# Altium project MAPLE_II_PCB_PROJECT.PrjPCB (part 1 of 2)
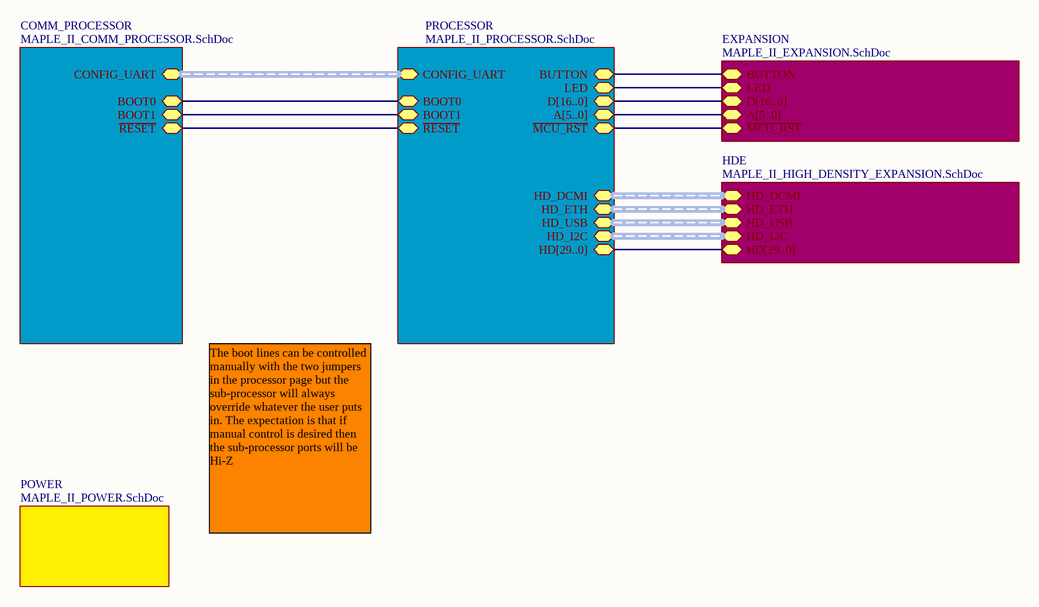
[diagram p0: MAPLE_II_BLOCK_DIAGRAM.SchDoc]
Revision: A; Number: Maple II; Engineer: Dave McCoy; Drawn: Dave McCoy; Company: Leaflabs LLC
6 sheets, 140 parts. Net scope: hierarchical (ports join the sheet entries above them; power ports are global).
Board file: MAPLE_II.PcbDoc
Sheets:
  MAPLE_II_BLOCK_DIAGRAM.SchDoc
    PROCESSOR = MAPLE_II_PROCESSOR.SchDoc
    COMM_PROCESSOR = MAPLE_II_COMM_PROCESSOR.SchDoc
    POWER = MAPLE_II_POWER.SchDoc
    EXPANSION = MAPLE_II_EXPANSION.SchDoc
    HDE = MAPLE_II_HIGH_DENSITY_EXPANSION.SchDoc

## Sheet MAPLE_II_BLOCK_DIAGRAM.SchDoc: Block Diagram
size B; CompanyName: LeafLabs; DrawnBy: David McCoy; Engineer: David McCoy; Organization: LeafLabs; DocumentNumber: 1; Revision: A; SheetNumber: 1; SheetTotal: 6; ProjectPrettyName: Maple II

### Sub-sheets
COMM_PROCESSOR = MAPLE_II_COMM_PROCESSOR.SchDoc: ~{RESET}, BOOT0, BOOT1, CONFIG_UART (harness UART_Harness)
EXPANSION = MAPLE_II_EXPANSION.SchDoc: BUTTON, LED, A[5..0], D[16..0], ~{MCU_RST}
HDE = MAPLE_II_HIGH_DENSITY_EXPANSION.SchDoc: HD_DCMI (harness DCMI_Harness), HD_ETH (harness ETH_RMII_Harness), HD_USB (harness USB_Harness), HD_I2C (harness I2C_Harness), HD[29..0]
POWER = MAPLE_II_POWER.SchDoc: no entries
PROCESSOR = MAPLE_II_PROCESSOR.SchDoc: ~{RESET}, BOOT0, BOOT1, CONFIG_UART (harness UART_Harness), BUTTON, LED, HD_DCMI (harness DCMI_Harness), HD_ETH (harness ETH_RMII_Harness), HD_USB (harness USB_Harness), HD_I2C (harness I2C_Harness), A[5..0], D[16..0], HD[29..0], ~{MCU_RST}

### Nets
BOOT0: sheet PROCESSOR/BOOT0, sheet PROCESSOR/BUTTON, sheet COMM_PROCESSOR/BOOT0, sheet EXPANSION/BUTTON
BOOT1: sheet PROCESSOR/BOOT1, sheet COMM_PROCESSOR/BOOT1
D13: sheet PROCESSOR/LED, sheet EXPANSION/LED
~{MCU_RST}: sheet PROCESSOR/~{MCU_RST}, sheet EXPANSION/~{MCU_RST}
NetR22_2: sheet PROCESSOR/~{RESET}, sheet COMM_PROCESSOR/~{RESET}

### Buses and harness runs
bus sheet EXPANSION/A[5..0] = sheet PROCESSOR/A[5..0]
bus sheet EXPANSION/D[16..0] = sheet PROCESSOR/D[16..0]
bus sheet HDE/HD[29..0] = sheet PROCESSOR/HD[29..0]
harness sheet COMM_PROCESSOR/CONFIG_UART = sheet PROCESSOR/CONFIG_UART
harness sheet HDE/HD_DCMI = sheet PROCESSOR/HD_DCMI
harness sheet HDE/HD_ETH = sheet PROCESSOR/HD_ETH
harness sheet HDE/HD_I2C = sheet PROCESSOR/HD_I2C
harness sheet HDE/HD_USB = sheet PROCESSOR/HD_USB

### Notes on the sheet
- The boot lines can be controlled manually with the two jumpers in the processor page but the sub-processor will always override whatever the user puts in. The expectation is that if manual control is desired then the sub-processor ports will be Hi-Z

## Sheet MAPLE_II_PROCESSOR.SchDoc: Processor
size B; CompanyName: LeafLabs; DrawnBy: David McCoy; Engineer: David McCoy; Organization: LeafLabs; DocumentNumber: 3; Revision: A; SheetNumber: 3; SheetTotal: 6; ProjectPrettyName: Maple II
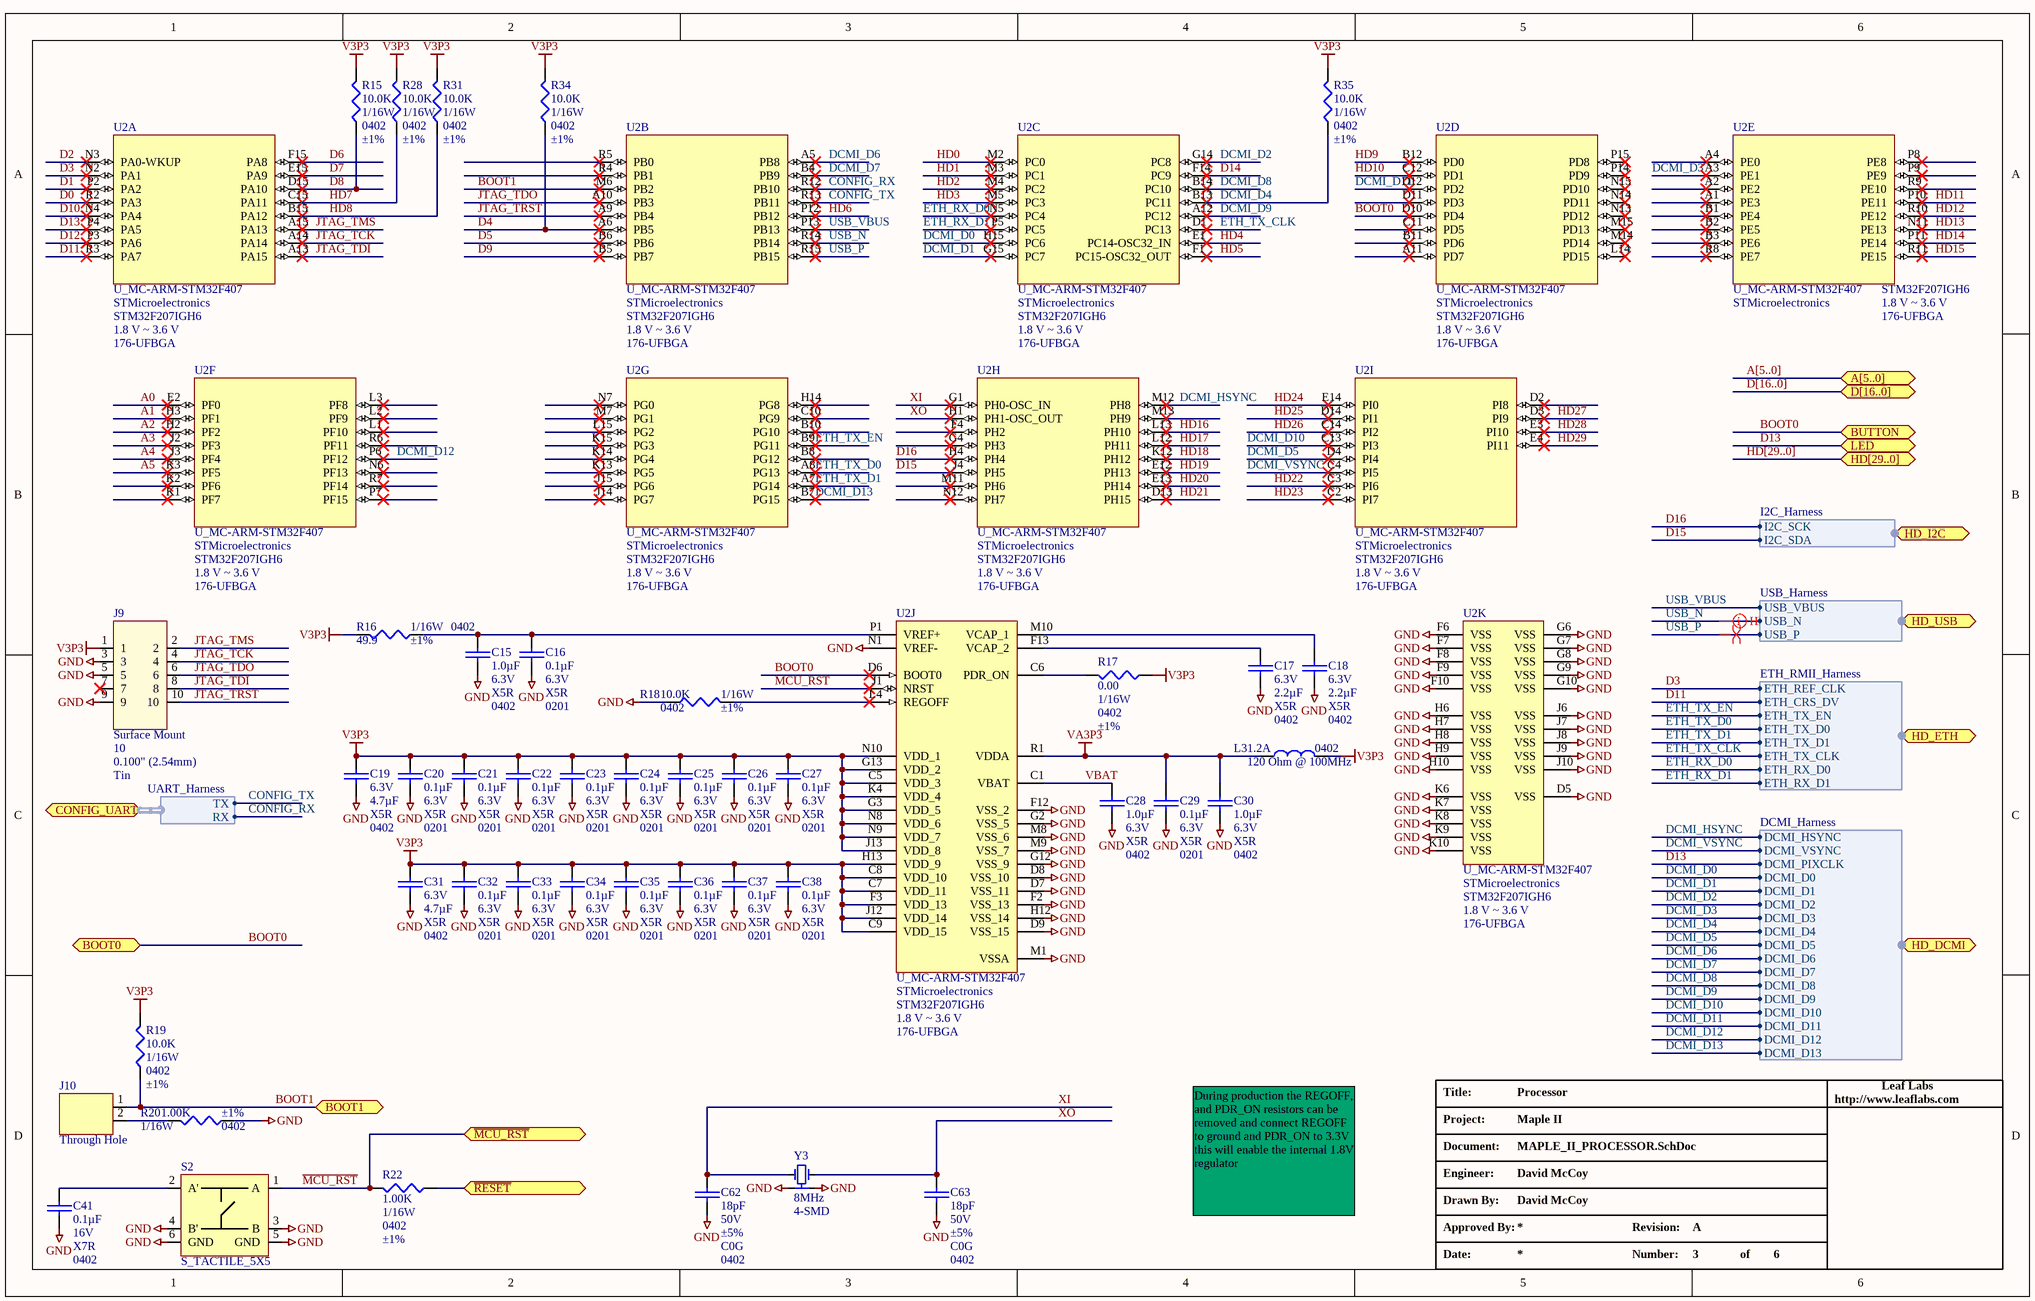
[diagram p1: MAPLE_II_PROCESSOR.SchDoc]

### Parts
(Parts that share a designator on the sheet are numbered #1, #2 ... from top to bottom, then left to right.)
C15  Capacitance: 1.0µF  Voltage - Rated: 6.3V  Temperature Coefficient: X5R  Package / Case: 0402  [CAPC0201]  (hidden comment: 1.0UF)
C16  Capacitance: 0.1µF  Voltage - Rated: 6.3V  Temperature Coefficient: X5R  Package / Case: 0201  [CAPC0201]  (hidden comment: 0.1UF)
C17  Voltage - Rated: 6.3V  Capacitance: 2.2µF  Temperature Coefficient: X5R  Package / Case: 0402  [C_ERA-0402]  (hidden comment: Capacitor 2.2uF 0402)
C18  Voltage - Rated: 6.3V  Capacitance: 2.2µF  Temperature Coefficient: X5R  Package / Case: 0402  [C_ERA-0402]  (hidden comment: Capacitor 2.2uF 0402)
C19  Voltage - Rated: 6.3V  Capacitance: 4.7µF  Temperature Coefficient: X5R  Package / Case: 0402  [C_ERA-0402]  (hidden comment: Capacitor  4.7uF 0402)
C20  Capacitance: 0.1µF  Voltage - Rated: 6.3V  Temperature Coefficient: X5R  Package / Case: 0201  [CAPC0201]  (hidden comment: 0.1UF)
C21  Capacitance: 0.1µF  Voltage - Rated: 6.3V  Temperature Coefficient: X5R  Package / Case: 0201  [CAPC0201]  (hidden comment: 0.1UF)
C22  Capacitance: 0.1µF  Voltage - Rated: 6.3V  Temperature Coefficient: X5R  Package / Case: 0201  [CAPC0201]  (hidden comment: 0.1UF)
C23  Capacitance: 0.1µF  Voltage - Rated: 6.3V  Temperature Coefficient: X5R  Package / Case: 0201  [CAPC0201]  (hidden comment: 0.1UF)
C24  Capacitance: 0.1µF  Voltage - Rated: 6.3V  Temperature Coefficient: X5R  Package / Case: 0201  [CAPC0201]  (hidden comment: 0.1UF)
C25  Capacitance: 0.1µF  Voltage - Rated: 6.3V  Temperature Coefficient: X5R  Package / Case: 0201  [CAPC0201]  (hidden comment: 0.1UF)
C26  Capacitance: 0.1µF  Voltage - Rated: 6.3V  Temperature Coefficient: X5R  Package / Case: 0201  [CAPC0201]  (hidden comment: 0.1UF)
C27  Capacitance: 0.1µF  Voltage - Rated: 6.3V  Temperature Coefficient: X5R  Package / Case: 0201  [CAPC0201]  (hidden comment: 0.1UF)
C28  Capacitance: 1.0µF  Voltage - Rated: 6.3V  Temperature Coefficient: X5R  Package / Case: 0402  [CAPC0201]  (hidden comment: 1.0UF)
C29  Capacitance: 0.1µF  Voltage - Rated: 6.3V  Temperature Coefficient: X5R  Package / Case: 0201  [CAPC0201]  (hidden comment: 0.1UF)
C30  Capacitance: 1.0µF  Voltage - Rated: 6.3V  Temperature Coefficient: X5R  Package / Case: 0402  [CAPC0201]  (hidden comment: 1.0UF)
C31  Voltage - Rated: 6.3V  Capacitance: 4.7µF  Temperature Coefficient: X5R  Package / Case: 0402  [C_ERA-0402]  (hidden comment: Capacitor  4.7uF 0402)
C32  Capacitance: 0.1µF  Voltage - Rated: 6.3V  Temperature Coefficient: X5R  Package / Case: 0201  [CAPC0201]  (hidden comment: 0.1UF)
C33  Capacitance: 0.1µF  Voltage - Rated: 6.3V  Temperature Coefficient: X5R  Package / Case: 0201  [CAPC0201]  (hidden comment: 0.1UF)
C34  Capacitance: 0.1µF  Voltage - Rated: 6.3V  Temperature Coefficient: X5R  Package / Case: 0201  [CAPC0201]  (hidden comment: 0.1UF)
C35  Capacitance: 0.1µF  Voltage - Rated: 6.3V  Temperature Coefficient: X5R  Package / Case: 0201  [CAPC0201]  (hidden comment: 0.1UF)
C36  Capacitance: 0.1µF  Voltage - Rated: 6.3V  Temperature Coefficient: X5R  Package / Case: 0201  [CAPC0201]  (hidden comment: 0.1UF)
C37  Capacitance: 0.1µF  Voltage - Rated: 6.3V  Temperature Coefficient: X5R  Package / Case: 0201  [CAPC0201]  (hidden comment: 0.1UF)
C38  Capacitance: 0.1µF  Voltage - Rated: 6.3V  Temperature Coefficient: X5R  Package / Case: 0201  [CAPC0201]  (hidden comment: 0.1UF)
C41  Capacitance: 0.1µF  Voltage - Rated: 16V  Temperature Coefficient: X7R  Package / Case: 0402  [C_ERA-0402]  (hidden comment: C_0402_0.1UF_16V)
C62  Capacitance: 18pF  Voltage - Rated: 50V  Tolerance: ±5%  Temperature Coefficient: C0G  Package / Case: 0402  [C_ERA-0402]  (hidden comment: Capacitor 18pF 0402)
C63  Capacitance: 18pF  Voltage - Rated: 50V  Tolerance: ±5%  Temperature Coefficient: C0G  Package / Case: 0402  [C_ERA-0402]  (hidden comment: Capacitor 18pF 0402)
J9  Mounting Type: Surface Mount  Number of Positions: 10  Pitch: 0.100" (2.54mm)  Contact Finish: Tin  [HDR_2X5_1.27MMSMD]  (hidden comment: J_HDR2X5_0.05_SMD)
J10  Mounting Type: Through Hole  [HDR_1X2]  (hidden comment: J_HDR1X2_JUMPER)
L3  Impedance @ Frequency: 120 Ohm @ 100MHz  Current Rating: 1.2A  Package / Case: 0402  [ERA-0402]  (hidden comment: L_FERRITE_120R_100MHZ)
R15  Resistance In Ohms: 10.0K  Power (Watts): 1/16W  Case: 0402  Tolerance: ±1%  [ERA-0402]  (hidden comment: R_0402_10.0K)
R16  Resistance (Ohms): 49.9  Power (Watts): 1/16W  Tolerance: ±1%  Package / Case: 0402  [ERA-0402]  (hidden comment: R_0402_49.9)
R17  Resistance In Ohms: 0.00  Power (Watts): 1/16W  Case: 0402  Tolerance: ±1%  [ERA-0402]  (hidden comment: R_0402_0.0)
R18  Resistance In Ohms: 10.0K  Power (Watts): 1/16W  Case: 0402  Tolerance: ±1%  [ERA-0402]  (hidden comment: R_0402_10.0K)
R19  Resistance In Ohms: 10.0K  Power (Watts): 1/16W  Case: 0402  Tolerance: ±1%  [ERA-0402]  (hidden comment: R_0402_10.0K)
R20  Resistance In Ohms: 1.00K  Power (Watts): 1/16W  Case: 0402  Tolerance: ±1%  [ERA-0402]  (hidden comment: R_0402_1.0K)
R22  Resistance In Ohms: 1.00K  Power (Watts): 1/16W  Case: 0402  Tolerance: ±1%  [ERA-0402]  (hidden comment: R_0402_1.0K)
R28  Resistance In Ohms: 10.0K  Power (Watts): 1/16W  Case: 0402  Tolerance: ±1%  [ERA-0402]  (hidden comment: R_0402_10.0K)
R31#1  Resistance In Ohms: 10.0K  Power (Watts): 1/16W  Case: 0402  Tolerance: ±1%  [ERA-0402]  (hidden comment: R_0402_10.0K)
R34#1  Resistance In Ohms: 10.0K  Power (Watts): 1/16W  Case: 0402  Tolerance: ±1%  [ERA-0402]  (hidden comment: R_0402_10.0K)
R35#1  Resistance In Ohms: 10.0K  Power (Watts): 1/16W  Case: 0402  Tolerance: ±1%  [ERA-0402]  (hidden comment: R_0402_10.0K)
S2  S_TACTILE_5X5  [TACTILE_BUTTON_5X5]
U2  U_MC-ARM-STM32F407  Manufacturer: STMicroelectronics  Manufacturer Part Number: STM32F207IGH6  Voltage - Supply (Vcc/Vdd): 1.8 V ~ 3.6 V  Package / Case: 176-UFBGA  [UFBGA176+25]  (parts A,B,C,D,E,F,G,H,I,J,K of 11)
Y3  Package / Case: 4-SMD  [SMD_OSC_8MHZ]  (hidden comment: 8MHz)

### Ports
A[5..0], BOOT0, BOOT1, BUTTON, CONFIG_UART (harness UART_Harness), D[16..0], HD[29..0], HD_DCMI (harness DCMI_Harness), HD_ETH (harness ETH_RMII_Harness), HD_I2C (harness I2C_Harness), HD_USB (harness USB_Harness), LED, ~{MCU_RST}, ~{RESET}

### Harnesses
UART_Harness: TX, RX
DCMI_Harness: DCMI_HSYNC, DCMI_VSYNC, DCMI_PIXCLK, DCMI_D0, DCMI_D1, DCMI_D2, DCMI_D3, DCMI_D4, DCMI_D5, DCMI_D6, DCMI_D7, DCMI_D8, DCMI_D9, DCMI_D10, DCMI_D11, DCMI_D12, DCMI_D13
ETH_RMII_Harness: ETH_REF_CLK, ETH_CRS_DV, ETH_TX_EN, ETH_TX_D0, ETH_TX_D1, ETH_TX_CLK, ETH_RX_D0, ETH_RX_D1
USB_Harness: USB_VBUS, USB_N, USB_P
I2C_Harness: I2C_SCK, I2C_SDA

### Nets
GND: C15.1 C16.1 C17.1 C18.1 C19.1 C20.1 C21.1 C22.1 C23.1 C24.1 C25.1 C26.1 C27.1 C28.1 C29.1 C30.1 C31.1 C32.1 C33.1 C34.1 C35.1 C36.1 C37.1 C38.1 C41.1 C62.1 C63.1 J9.3 J9.5 J9.9 R18.2 R20.2 S2.3(B) S2.4(B') S2.5(GND) S2.6(GND) U2.D5(VSS) U2.D7(VSS_11) U2.D8(VSS_10) U2.D9(VSS_15) U2.F2(VSS_13) U2.F6(VSS) U2.F7(VSS) U2.F8(VSS) U2.F9(VSS) U2.F10(VSS) U2.F12(VSS_2) U2.G2(VSS_5) U2.G6(VSS) U2.G7(VSS) U2.G8(VSS) U2.G9(VSS) U2.G10(VSS) U2.G12(VSS_9) U2.H6(VSS) U2.H7(VSS) U2.H8(VSS) U2.H9(VSS) U2.H10(VSS) U2.H12(VSS_14) U2.J6(VSS) U2.J7(VSS) U2.J8(VSS) U2.J9(VSS) U2.J10(VSS) U2.K6(VSS) U2.K7(VSS) U2.K8(VSS) U2.K9(VSS) U2.K10(VSS) U2.M1(VSSA) U2.M8(VSS_6) U2.M9(VSS_7) U2.N1(VREF-) Y3.2 Y3.4
V3P3: C19.2 C20.2 C21.2 C22.2 C23.2 C24.2 C25.2 C26.2 C27.2 C31.2 C32.2 C33.2 C34.2 C35.2 C36.2 C37.2 C38.2 J9.1 L3.2 R15.1 R16.1 R17.2 R19.2 R28.1 R31#1.1 R34#1.1 R35#1.1 U2.C5(VDD_3) U2.C7(VDD_11) U2.C8(VDD_10) U2.C9(VDD_15) U2.F3(VDD_13) U2.G3(VDD_5) U2.G13(VDD_2) U2.H13(VDD_9) U2.J12(VDD_14) U2.J13(VDD_8) U2.K4(VDD_4) U2.N8(VDD_6) U2.N9(VDD_7) U2.N10(VDD_1)
VA3P3: C29.2 C30.2 L3.1 U2.R1(VDDA)
A0: U2.E2(PF0)
A1: U2.H3(PF1)
A2: U2.H2(PF2)
A3: U2.J2(PF3)
A4: U2.J3(PF4)
A5: U2.K3(PF5)
BOOT0: U2.D6(BOOT0) U2.D10(PD4) ; port BOOT0, port BUTTON
BOOT1: J10.1 R19.1 U2.M6(PB2) ; port BOOT1
CONFIG_RX: U2.R12(PB10) ; port CONFIG_UART.RX  [project net COMM_UART1_RX]
CONFIG_TX: U2.R13(PB11) ; port CONFIG_UART.TX  [project net COMM_UART1_TX]
D0: U2.R2(PA3)
D1: U2.P2(PA2)
D2: U2.N3(PA0-WKUP)
D3: U2.N2(PA1) ; port HD_ETH.ETH_REF_CLK
D4: R34#1.2 U2.A6(PB5)
D5: U2.B6(PB6)
D6: U2.F15(PA8)
D7: U2.E15(PA9)
D8: R15.2 U2.D15(PA10)
D9: U2.B5(PB7)
D10: U2.N4(PA4)
D11: U2.R3(PA7) ; port HD_ETH.ETH_CRS_DV
D12: U2.P3(PA6)
D13: U2.P4(PA5) ; port LED, port HD_DCMI.DCMI_PIXCLK
D14: U2.F14(PC9)
D15: U2.J4(PH5) ; port HD_I2C.I2C_SDA
D16: U2.H4(PH4) ; port HD_I2C.I2C_SCK
DCMI_D0: U2.H15(PC6) ; port HD_DCMI.DCMI_D0
DCMI_D1: U2.G15(PC7) ; port HD_DCMI.DCMI_D1
DCMI_D2: U2.G14(PC8) ; port HD_DCMI.DCMI_D2
DCMI_D3: U2.A3(PE1) ; port HD_DCMI.DCMI_D3
DCMI_D4: R35#1.2 U2.B13(PC11) ; port HD_DCMI.DCMI_D4
DCMI_D5: U2.D4(PI4) ; port HD_DCMI.DCMI_D5
DCMI_D6: U2.A5(PB8) ; port HD_DCMI.DCMI_D6
DCMI_D7: U2.B4(PB9) ; port HD_DCMI.DCMI_D7
DCMI_D8: U2.B14(PC10) ; port HD_DCMI.DCMI_D8
DCMI_D9: U2.A12(PC12) ; port HD_DCMI.DCMI_D9
DCMI_D10: U2.C13(PI3) ; port HD_DCMI.DCMI_D10
DCMI_D11: U2.D12(PD2) ; port HD_DCMI.DCMI_D11
DCMI_D12: U2.P6(PF12) ; port HD_DCMI.DCMI_D12
DCMI_D13: U2.B7(PG15) ; port HD_DCMI.DCMI_D13
DCMI_HSYNC: U2.M12(PH8) ; port HD_DCMI.DCMI_HSYNC
DCMI_VSYNC: U2.C4(PI5) ; port HD_DCMI.DCMI_VSYNC
ETH_RX_D0: U2.N5(PC4) ; port HD_ETH.ETH_RX_D0
ETH_RX_D1: U2.P5(PC5) ; port HD_ETH.ETH_RX_D1
ETH_TX_CLK: U2.D1(PC13) ; port HD_ETH.ETH_TX_CLK
ETH_TX_D0: U2.A8(PG13) ; port HD_ETH.ETH_TX_D0
ETH_TX_D1: U2.A7(PG14) ; port HD_ETH.ETH_TX_D1
ETH_TX_EN: U2.B9(PG11) ; port HD_ETH.ETH_TX_EN
HD0: U2.M2(PC0)
HD1: U2.M3(PC1)
HD2: U2.M4(PC2)
HD3: U2.M5(PC3)
HD4: U2.E1(PC14-OSC32_IN)
HD5: U2.F1(PC15-OSC32_OUT)
HD6: U2.P12(PB12)
HD7: R28.2 U2.C15(PA11)
HD8: R31#1.2 U2.B15(PA12)
HD9: U2.B12(PD0)
HD10: U2.C12(PD1)
HD11: U2.P10(PE11)
HD12: U2.R10(PE12)
HD13: U2.N11(PE13)
HD14: U2.P11(PE14)
HD15: U2.R11(PE15)
HD16: U2.L13(PH10)
HD17: U2.L12(PH11)
HD18: U2.K12(PH12)
HD19: U2.E12(PH13)
HD20: U2.E13(PH14)
HD21: U2.D13(PH15)
HD22: U2.C3(PI6)
HD23: U2.C2(PI7)
HD24: U2.E14(PI0)
HD25: U2.D14(PI1)
HD26: U2.C14(PI2)
HD27: U2.D3(PI9)
HD28: U2.E3(PI10)
HD29: U2.E4(PI11)
JTAG_TCK: J9.4 U2.A14(PA14)
JTAG_TDI: J9.8 U2.A13(PA15)
JTAG_TDO: J9.6 U2.A10(PB3)
JTAG_TMS: J9.2 U2.A15(PA13)
JTAG_TRST: J9.10 U2.A9(PB4)
~{MCU_RST}: R22.1 S2.1(A) U2.J1(NRST) ; port ~{MCU_RST}
USB_N: U2.R14(PB14) ; port HD_USB.USB_N
USB_P: U2.R15(PB15) ; port HD_USB.USB_P
USB_VBUS: U2.P13(PB13) ; port HD_USB.USB_VBUS
VBAT: C28.2 U2.C1(VBAT)
XI: C62.2 U2.G1(PH0-OSC_IN) Y3.1
XO: C63.2 U2.H1(PH1-OSC_OUT) Y3.3
NetC15_2: C15.2 C16.2 R16.2 U2.P1(VREF+)
NetC17_2: C17.2 U2.F13(VCAP_2)
NetC18_2: C18.2 U2.M10(VCAP_1)
NetC41_2: C41.2 S2.2(A')
NetJ10_2: J10.2 R20.1
NetR17_1: R17.1 U2.C6(PDR_ON)
NetR18_1: R18.1 U2.L4(REGOFF)
NetR22_2: R22.2 ; port ~{RESET}

Not connected (* = marked no-connect by the designer): J9 7*; U2 A1(PE3)* A2(PE2)* A4(PE0)* A11(PD7)* B1(PE4)* B2(PE5)* B3(PE6)* B8(PG12)* B10(PG10)* B11(PD6)* C10(PG9)* C11(PD5)* D2(PI8)* D11(PD3)* F4(PH2)* G4(PH3)* H14(PG8)* J14(PG7)* J15(PG6)* K1(PF7)* K2(PF6)* K13(PG5)* K14(PG4)* K15(PG3)* L1(PF10)* L2(PF9)* L3(PF8)* L14(PD15)* L15(PG2)* M7(PG1)* M11(PH6)* M13(PH9)* M14(PD14)* M15(PD13)* N6(PF13)* N7(PG0)* N12(PH7)* N13(PD12)* N14(PD11)* N15(PD10)* P7(PF15)* P8(PE8)* P9(PE9)* P14(PD9)* P15(PD8)* R4(PB1)* R5(PB0)* R6(PF11)* R7(PF14)* R8(PE7)* R9(PE10)*

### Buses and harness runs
bus A[5..0] = port A[5..0]
bus D[16..0] = port D[16..0]
bus HD[29..0] = port HD[29..0]

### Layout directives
differential pair: USB_N, USB_P

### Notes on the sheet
- Peripherals Used:
  SPI1: COMM Processor
  SPI2: used for expansion
  USART1:
  USART2:
  USART3: COMM/Config
  USART4:
  USART5:
  USART6:
  I2C1:
  I2C2:
- PA9 is used for USB bootup... but what is it for?
- (near U2) VBAT can be used to power the chip in a low power mode
- (near C16) What are the pullup pins for the configuration I/O
  for example in order to run USART1 as the configuration path, a USB line needs to be pulled up and the CAN needs to be pulled up
- Boot Modes:
  BOOT [1, 0] = X,0 : User Flash
  BOOT [1, 0] = 0, 1 : System memory
  BOOT [1, 0] = 1, 1 : Embedded SRAM (default)
- Put on header to pull down manually
- break out TIMER1, 2 and 5 if possible, they offer the most functionality
- During production the REGOFF, and PDR_ON resistors can be removed and connect REGOFF to ground and PDR_ON to 3.3V this will enable the internal 1.8V regulator

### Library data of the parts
C15 C28 C30 = C_0201_1.0UF: CAP CER 1UF 6.3V 20% X5R 0201; Manufacturer: TDK Corporation; Manufacturer Part Number: C0603X5R0J105M
C16 C20-C27 C29 C32-C38 = C_0201_0.1UF: CAP CER 0.1UF 6.3V 10% X5R 0201; Manufacturer: TDK Corporation; Manufacturer Part Number: C0603X5R0J104K
C17 C18 = C_0402_2.2UF: CAP CER 2.2UF 6.3V X5R 0402; Manufacturer: TDK Corporation; Manufacturer Part Number: C1005X5R0J225M; Tolerance: ±20%
C19 C31 = C_0402_4.7UF: CAP CER 4.7UF 6.3V X5R 0402; Manufacturer: Murata Electronics North America; Manufacturer Part Number: GRM155R60J475ME87D; Tolerance: ±20%
C41 = C_0402_0.1UF_16V: CAP CER .10UF 16V X7R 0402; Manufacturer: TDK Corporation; Manufacturer Part Number: C1005X7R1C104K; Tolerance: ±10%
C62 C63 = C_0402_18PF_50V: CAP CER 18PF 50V C0G 5% 0402; Manufacturer: TDK Corporation; Manufacturer Part Number: C1005C0G1H180J
J9 = J_HDR2X5_0.05_SMD: CONN HEADER 10POS DL UNSHRD SMD; Manufacturer: FCI; Manufacturer Part Number: 20021121-00010C4LF; Connector Type: Unshrouded; Number of Positions Loaded: All; Row Spacing: 0.050" (1.27mm); Molding Height Above Board: 0.044" (1.10mm)
J10 = J_HDR1X2_JUMPER: CONN HEADER .100" 12POS TIN PCB; Manufacturer: Samtec Inc; Manufacturer Part Number: TS-112-T-A; Number of Positions: 2; Connector Type: Unshrouded; Number of Positions Loaded: All; Pitch: 0.100" (2.54mm); NOTE: This is a 1X12 header
L3 = L_FERRITE_120R_100MHZ: FERRITE CHIP 120 OHM 1.2A 0402; Manufacturer: TDK Corporation; Manufacturer Part Number: MPZ1005S121C; DC Resistance (DCR): 90 mOhm Max; Filter Type: Differential Mode - Single; Number of Lines: 1
R15 R18 R19 R28 R31#1 R34#1 R35#1 = R_0402_10.0K: RES 10.0K OHM 1/16W 1% 0402 SMD; Manufacturer: Vishay/Dale; Manufacturer Part Number: CRCW040210K0FKED; Temperature Coefficient: ±100ppm/°C
R16 = R_0402_49.9: RES 49.9 OHM 1/16W 1% 0402 SMD; Manufacturer: Stackpole Electronics Inc; Manufacturer Part Number: RMCF0402FT49R9; Temperature Coefficient: ±200ppm/°C
R17 = R_0402_0.00: RES 1.00 OHM 1/16W 1% 0402 SMD; Manufacturer: Panasonic - ECG; Manufacturer Part Number: ERJ-2GE0R00X; Description: RES 0.0 OHM 1/10W 0402 SMD; Resistance (Ohms): 0.0; Temperature Coefficient: -100/ +600ppm/°C
R20 R22 = R_0402_1.0K: RES 1.00K OHM 1/16W 1% 0402 SMD; Manufacturer: Vishay/Dale; Manufacturer Part Number: CRCW04021K00FKED; Temperature Coefficient: ±100ppm/°C
S2 = S_TACTILE_5X5: SWITCH LT 1.5MM HT 160GF SMD; Manufacturer: Panasonic - ECG; Manufacturer Part Number: EVQ-PLHA15; Circuit: SPST-NO; Switch Function: Off-Mom; Contact Rating @ Voltage: 0.02A @ 15VDC; Actuator Type: Standard; Outline: 4.90mm x 4.90mm; Illumination: Non-Illuminated
U2 = U_MC-ARM-STM32F407: MCU ARM 1024KB FLASH 176UFBGA; Core Processor: ARM® Cortex-M3™; Core Size: 32-Bit; Speed: 120MHz; Connectivity: CAN, Ethernet, I²C, IrDA, LIN, MMC, SPI, UART/USART, USB OTG; Peripherals: Brown-out Detect/Reset, DMA, I²S, LCD, POR, PWM, WDT; Number of I /O: 140; Program Memory Size: 1MB (1M x 8); RAM Size: 132K x 8; Data Converters: A/D 24x12b; D/A 2x12b; Oscillator Type: Internal
Y3 = Y_SMD_8.00MHZ_10PF: CRYSTAL 8.000 MHZ 10PF SMD; Manufacturer: Abracon Corporation; Manufacturer Part Number: ABM3B-8.000MHZ-10-1-U-T; Frequency Stability: ±10ppm; Operating Mode: Fundamental

## Sheet MAPLE_II_COMM_PROCESSOR.SchDoc: Communication Processor
size B; CompanyName: LeafLabs; DrawnBy: David McCoy; Engineer: David McCoy; Organization: LeafLabs; DocumentNumber: 2; Revision: A; SheetNumber: 2; SheetTotal: 6; ProjectPrettyName: Maple II
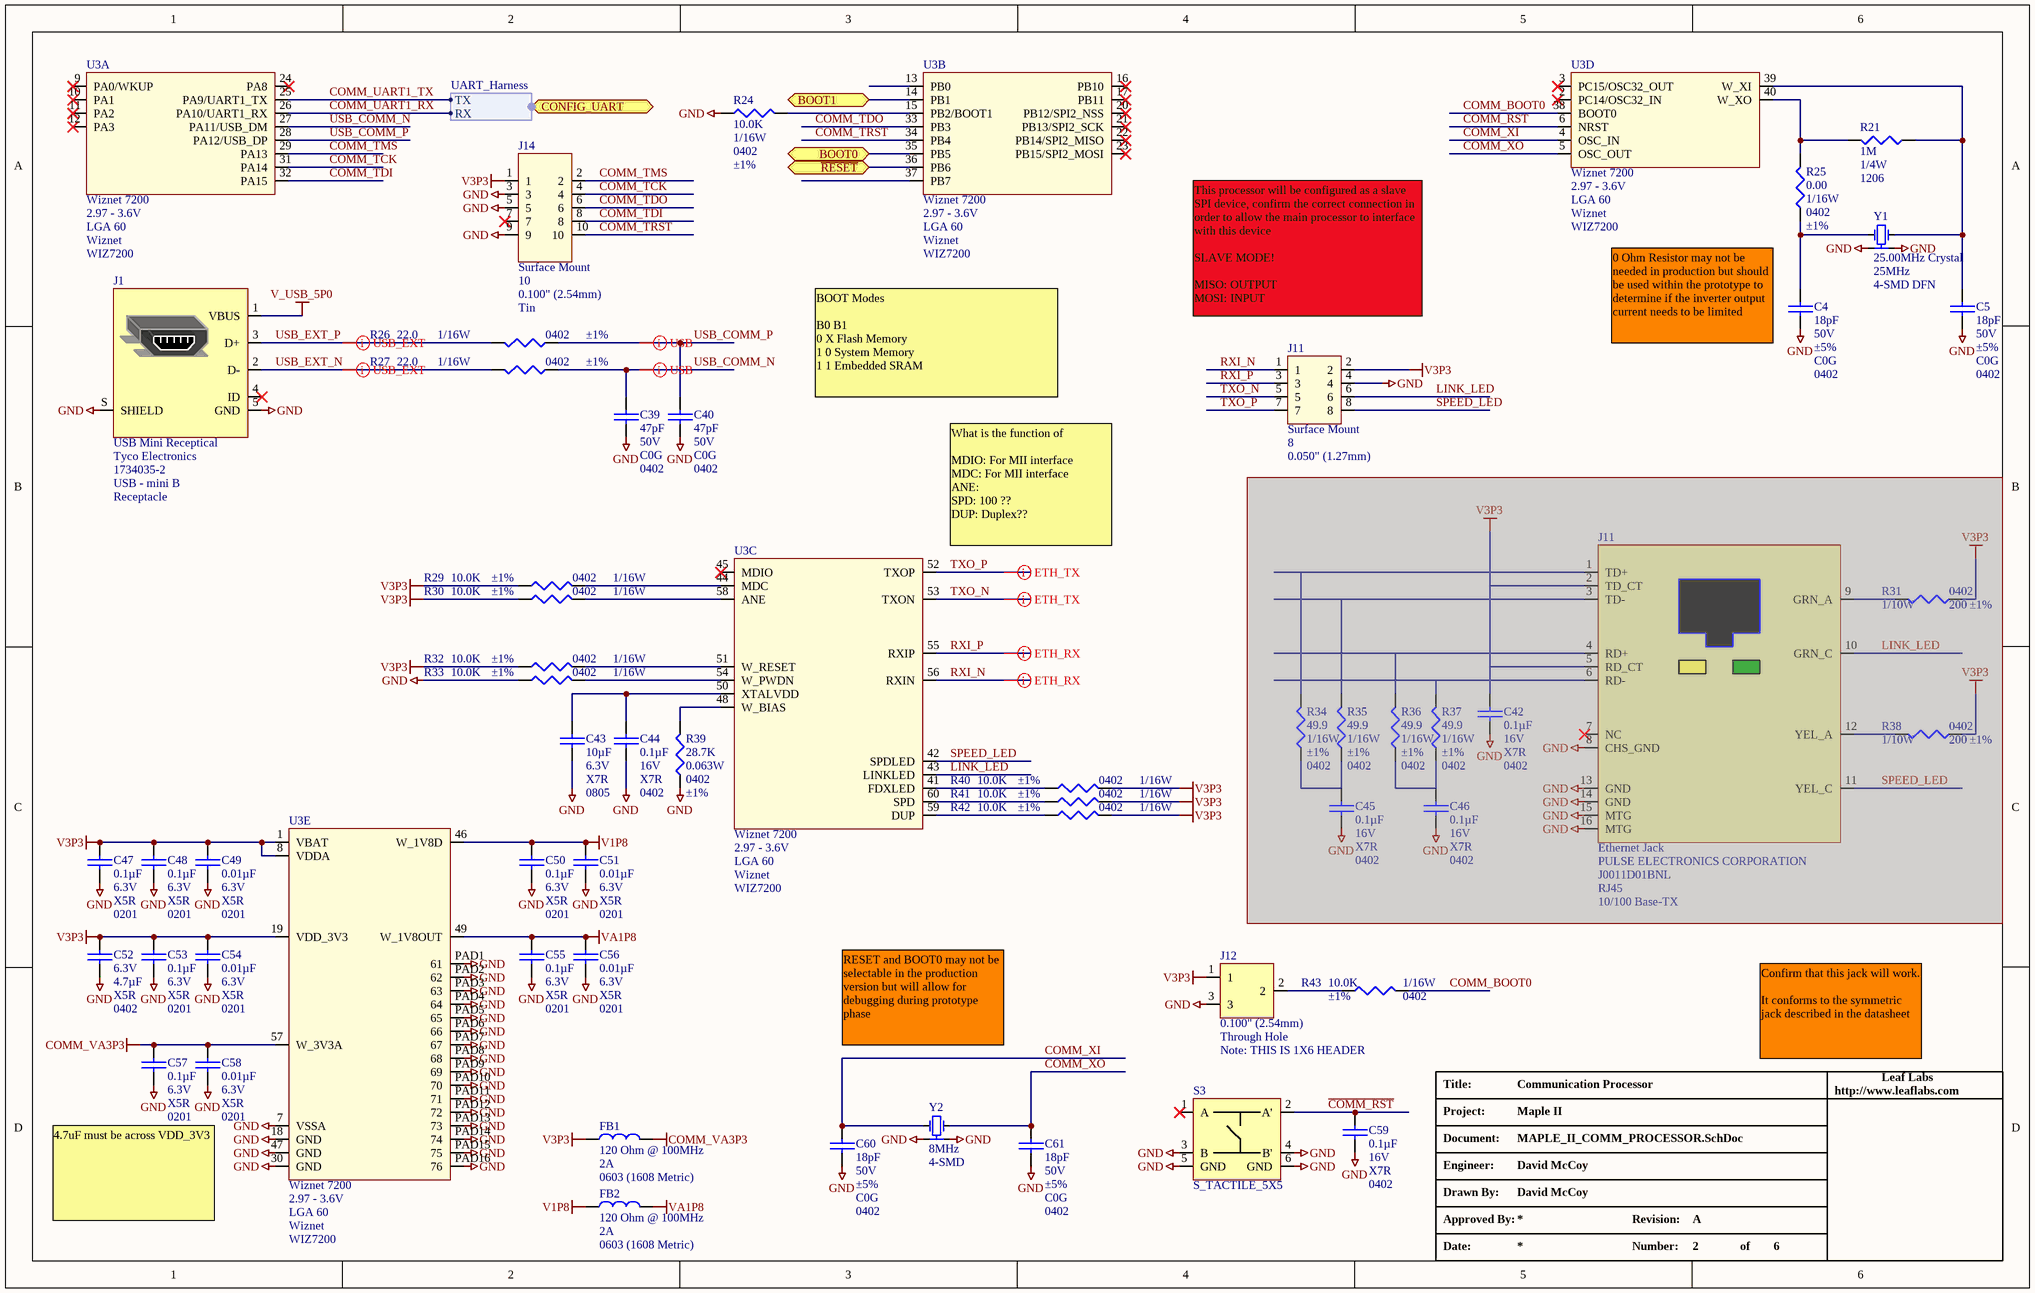
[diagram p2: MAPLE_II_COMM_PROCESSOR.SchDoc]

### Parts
(Parts that share a designator on the sheet are numbered #1, #2 ... from top to bottom, then left to right.)
C4  Capacitance: 18pF  Voltage - Rated: 50V  Tolerance: ±5%  Temperature Coefficient: C0G  Package / Case: 0402  [C_ERA-0402]  (hidden comment: Capacitor 18pF)
C5  Capacitance: 18pF  Voltage - Rated: 50V  Tolerance: ±5%  Temperature Coefficient: C0G  Package / Case: 0402  [C_ERA-0402]  (hidden comment: Capacitor 18pF)
C39  Capacitance: 47pF  Voltage - Rated: 50V  Temperature Coefficient: C0G  Package / Case: 0402  [C_ERA-0402]  (hidden comment: Capacitor 47pF 0402 50V)
C40  Capacitance: 47pF  Voltage - Rated: 50V  Temperature Coefficient: C0G  Package / Case: 0402  [C_ERA-0402]  (hidden comment: Capacitor 47pF 0402 50V)
C42  Capacitance: 0.1µF  Voltage - Rated: 16V  Temperature Coefficient: X7R  Package / Case: 0402  [C_ERA-0402]  (hidden comment: Capacitor 0.1uF 0402 16V)  (masked out: inside a compile mask, not in the netlist)
C43  Capacitance: 10µF  Voltage - Rated: 6.3V  Temperature Coefficient: X7R  Package / Case: 0805  [C_ERA-0805]  (hidden comment: C_0805_10uF_25V)
C44  Capacitance: 0.1µF  Voltage - Rated: 16V  Temperature Coefficient: X7R  Package / Case: 0402  [C_ERA-0402]  (hidden comment: Capacitor 0.1uF 0402 16V)
C45  Capacitance: 0.1µF  Voltage - Rated: 16V  Temperature Coefficient: X7R  Package / Case: 0402  [C_ERA-0402]  (hidden comment: Capacitor 0.1uF 0402 16V)  (masked out: inside a compile mask, not in the netlist)
C46  Capacitance: 0.1µF  Voltage - Rated: 16V  Temperature Coefficient: X7R  Package / Case: 0402  [C_ERA-0402]  (hidden comment: Capacitor 0.1uF 0402 16V)  (masked out: inside a compile mask, not in the netlist)
C47  Capacitance: 0.1µF  Voltage - Rated: 6.3V  Temperature Coefficient: X5R  Package / Case: 0201  [CAPC0201]  (hidden comment: 0.1UF)
C48  Capacitance: 0.1µF  Voltage - Rated: 6.3V  Temperature Coefficient: X5R  Package / Case: 0201  [CAPC0201]  (hidden comment: 0.1UF)
C49  Capacitance: 0.01µF  Voltage - Rated: 6.3V  Temperature Coefficient: X5R  Package / Case: 0201  [CAPC0201]  (hidden comment: 0.01UF)
C50  Capacitance: 0.1µF  Voltage - Rated: 6.3V  Temperature Coefficient: X5R  Package / Case: 0201  [CAPC0201]  (hidden comment: 0.1UF)
C51  Capacitance: 0.01µF  Voltage - Rated: 6.3V  Temperature Coefficient: X5R  Package / Case: 0201  [CAPC0201]  (hidden comment: 0.01UF)
C52  Voltage - Rated: 6.3V  Capacitance: 4.7µF  Temperature Coefficient: X5R  Package / Case: 0402  [C_ERA-0402]  (hidden comment: Capacitor  4.7uF 0402)
C53  Capacitance: 0.1µF  Voltage - Rated: 6.3V  Temperature Coefficient: X5R  Package / Case: 0201  [CAPC0201]  (hidden comment: 0.1UF)
C54  Capacitance: 0.01µF  Voltage - Rated: 6.3V  Temperature Coefficient: X5R  Package / Case: 0201  [CAPC0201]  (hidden comment: 0.01UF)
C55  Capacitance: 0.1µF  Voltage - Rated: 6.3V  Temperature Coefficient: X5R  Package / Case: 0201  [CAPC0201]  (hidden comment: 0.1UF)
C56  Capacitance: 0.01µF  Voltage - Rated: 6.3V  Temperature Coefficient: X5R  Package / Case: 0201  [CAPC0201]  (hidden comment: 0.01UF)
C57  Capacitance: 0.1µF  Voltage - Rated: 6.3V  Temperature Coefficient: X5R  Package / Case: 0201  [CAPC0201]  (hidden comment: 0.1UF)
C58  Capacitance: 0.01µF  Voltage - Rated: 6.3V  Temperature Coefficient: X5R  Package / Case: 0201  [CAPC0201]  (hidden comment: 0.01UF)
C59  Capacitance: 0.1µF  Voltage - Rated: 16V  Temperature Coefficient: X7R  Package / Case: 0402  [C_ERA-0402]  (hidden comment: Capacitor 0.1uF 0402 16V)
C60  Capacitance: 18pF  Voltage - Rated: 50V  Tolerance: ±5%  Temperature Coefficient: C0G  Package / Case: 0402  [C_ERA-0402]  (hidden comment: Capacitor 18pF 0402)
C61  Capacitance: 18pF  Voltage - Rated: 50V  Tolerance: ±5%  Temperature Coefficient: C0G  Package / Case: 0402  [C_ERA-0402]  (hidden comment: Capacitor 18pF 0402)
FB1  Impedance @ Frequency: 120 Ohm @ 100MHz  Current Rating: 2A  Package / Case: 0603 (1608 Metric)  [C_ERA-0603]  (hidden comment: Ferrite Bead 120 Ohms @ 100MHz)
FB2  Impedance @ Frequency: 120 Ohm @ 100MHz  Current Rating: 2A  Package / Case: 0603 (1608 Metric)  [C_ERA-0603]  (hidden comment: Ferrite Bead 120 Ohms @ 100MHz)
J1  USB Mini Receptical  Manufacturer: Tyco Electronics  Manufacturer Part Number: 1734035-2  Connector Type: USB - mini B  Gender: Receptacle  [MINI_USB_RECEPTICAL]
J11#1  Mounting Type: Surface Mount  Number of Positions: 8  Pitch: 0.050" (1.27mm)  [HDR_2X4_1.27RECP_SMD]  (hidden comment: J_HDR2X4_0.05_RCP_SMD)
J11#2  Ethernet Jack  Manufacturer: PULSE ELECTRONICS CORPORATION  Manufacturer Part Number: J0011D01BNL  Connector Type: RJ45  Speed: 10/100 Base-TX  [ETH_JACK_J0011D01BN]  (masked out: inside a compile mask, not in the netlist)
J12  Pitch: 0.100" (2.54mm)  Mounting Type: Through Hole  Note: THIS IS 1X6 HEADER  [HDR_1X3]  (hidden comment: J_HDR1X3_JUMPER_SELECT)
J14  Mounting Type: Surface Mount  Number of Positions: 10  Pitch: 0.100" (2.54mm)  Contact Finish: Tin  [HDR_2X5_1.27MMSMD]  (hidden comment: J_HDR2X5_0.05_SMD)
R21  Resistance In Ohms: 1M  Power (Watts): 1/4W  Case: 1206  [R_ERA-1206]  (hidden comment: R_1206_1.0M)
R24  Resistance In Ohms: 10.0K  Power (Watts): 1/16W  Case: 0402  Tolerance: ±1%  [ERA-0402]  (hidden comment: R_0402_10.0K)
R25  Resistance In Ohms: 0.00  Power (Watts): 1/16W  Case: 0402  Tolerance: ±1%  [ERA-0402]  (hidden comment: R_0402_0.0)
R26  Resistance In Ohms: 22.0  Power (Watts): 1/16W  Tolerance: ±1%  Case: 0402  [ERA-0402]  (hidden comment: R_0402_22.0)
R27  Resistance In Ohms: 22.0  Power (Watts): 1/16W  Tolerance: ±1%  Case: 0402  [ERA-0402]  (hidden comment: R_0402_22.0)
R29  Resistance In Ohms: 10.0K  Power (Watts): 1/16W  Case: 0402  Tolerance: ±1%  [ERA-0402]  (hidden comment: R_0402_10.0K)
R30  Resistance In Ohms: 10.0K  Power (Watts): 1/16W  Case: 0402  Tolerance: ±1%  [ERA-0402]  (hidden comment: R_0402_10.0K)
R31#2  Case: 0402  Resistance In Ohms: 200  Power (Watts): 1/10W  Tolerance: ±1%  [ERA-0402]  (hidden comment: R_0402_200.0)  (masked out: inside a compile mask, not in the netlist)
R32  Resistance In Ohms: 10.0K  Power (Watts): 1/16W  Case: 0402  Tolerance: ±1%  [ERA-0402]  (hidden comment: R_0402_10.0K)
R33  Resistance In Ohms: 10.0K  Power (Watts): 1/16W  Case: 0402  Tolerance: ±1%  [ERA-0402]  (hidden comment: R_0402_10.0K)
R34#2  Resistance (Ohms): 49.9  Power (Watts): 1/16W  Tolerance: ±1%  Package / Case: 0402  [ERA-0402]  (hidden comment: R_0402_49.9)  (masked out: inside a compile mask, not in the netlist)
R35#2  Resistance (Ohms): 49.9  Power (Watts): 1/16W  Tolerance: ±1%  Package / Case: 0402  [ERA-0402]  (hidden comment: R_0402_49.9)  (masked out: inside a compile mask, not in the netlist)
R36  Resistance (Ohms): 49.9  Power (Watts): 1/16W  Tolerance: ±1%  Package / Case: 0402  [ERA-0402]  (hidden comment: R_0402_49.9)  (masked out: inside a compile mask, not in the netlist)
R37  Resistance (Ohms): 49.9  Power (Watts): 1/16W  Tolerance: ±1%  Package / Case: 0402  [ERA-0402]  (hidden comment: R_0402_49.9)  (masked out: inside a compile mask, not in the netlist)
R38  Case: 0402  Resistance In Ohms: 200  Power (Watts): 1/10W  Tolerance: ±1%  [ERA-0402]  (hidden comment: R_0402_200.0)  (masked out: inside a compile mask, not in the netlist)
R39  Resistance In Ohms: 28.7K  Power (Watts): 0.063W  Case: 0402  Tolerance: ±1%  [ERA-0402]  (hidden comment: R_0402_28.7K)
R40  Resistance In Ohms: 10.0K  Power (Watts): 1/16W  Case: 0402  Tolerance: ±1%  [ERA-0402]  (hidden comment: R_0402_10.0K)
R41  Resistance In Ohms: 10.0K  Power (Watts): 1/16W  Case: 0402  Tolerance: ±1%  [ERA-0402]  (hidden comment: R_0402_10.0K)
R42  Resistance In Ohms: 10.0K  Power (Watts): 1/16W  Case: 0402  Tolerance: ±1%  [ERA-0402]  (hidden comment: R_0402_10.0K)
R43  Resistance In Ohms: 10.0K  Power (Watts): 1/16W  Case: 0402  Tolerance: ±1%  [ERA-0402]  (hidden comment: R_0402_10.0K)
S3  S_TACTILE_5X5  [TACTILE_BUTTON_5X5]
U3  Wiznet 7200  VOLTAGE: 2.97 - 3.6V  PACKAGE: LGA 60  Manufacturer: Wiznet  Manufacturer Part Number: WIZ7200  [LCCS55P1000X1000X150-60L]  (parts A,B,C,D,E of 5)
Y1  25.00MHz Crystal  Frequency: 25MHz  Package / Case: 4-SMD DFN  [LCCS220P500X320X105-4L]
Y2  Package / Case: 4-SMD  [SMD_OSC_8MHZ]  (hidden comment: 8MHz)

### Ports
BOOT0, BOOT1, CONFIG_UART (harness UART_Harness), ~{RESET}

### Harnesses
UART_Harness: TX, RX

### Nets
COMM_VA3P3: C57.2 C58.2 FB1.2 U3.57(W_3V3A)
GND: C4.1 C5.1 C39.1 C40.1 C43.1 C44.1 C47.1 C48.1 C49.1 C50.1 C51.1 C52.1 C53.1 C54.1 C55.1 C56.1 C57.1 C58.1 C59.1 C60.1 C61.1 J1.5(GND) J1.S(SHIELD) J11#1.4 J12.3 J14.3 J14.5 J14.9 R24.2 R33.2 R39.2 S3.3(B) S3.4(B') S3.5(GND) S3.6(GND) U3.7(VSSA) U3.18(GND) U3.30(GND) U3.47(GND) U3.PAD1(61) U3.PAD2(62) U3.PAD3(63) U3.PAD4(64) U3.PAD5(65) U3.PAD6(66) U3.PAD7(67) U3.PAD8(68) U3.PAD9(69) U3.PAD10(70) U3.PAD11(71) U3.PAD12(72) U3.PAD13(73) U3.PAD14(74) U3.PAD15(75) U3.PAD16(76) Y1.2 Y1.4 Y2.2 Y2.4
V1P8: C50.2 C51.2 FB2.1 U3.46(W_1V8D)
V3P3: C47.2 C48.2 C49.2 C52.2 C53.2 C54.2 FB1.1 J11#1.2 J12.1 J14.1 R29.2 R30.2 R32.2 R40.1 R41.1 R42.1 U3.1(VBAT) U3.8(VDDA) U3.19(VDD_3V3)
V_USB_5P0: J1.1(VBUS)
VA1P8: C55.2 C56.2 FB2.2 U3.49(W_1V8OUT)
BOOT0: U3.35(PB5) ; port BOOT0
BOOT1: U3.14(PB1) ; port BOOT1
~{COMM_RST}: C59.2 S3.2(A') U3.6(NRST)
COMM_BOOT0: R43.2 U3.38(BOOT0)
COMM_TCK: J14.4 U3.31(PA14)
COMM_TDI: J14.8 U3.32(PA15)
COMM_TDO: J14.6 U3.33(PB3)
COMM_TMS: J14.2 U3.29(PA13)
COMM_TRST: J14.10 U3.34(PB4)
COMM_UART1_RX: U3.26(PA10/UART1_RX) ; port CONFIG_UART.RX
COMM_UART1_TX: U3.25(PA9/UART1_TX) ; port CONFIG_UART.TX
COMM_XI: C60.2 U3.4(OSC_IN) Y2.1
COMM_XO: C61.2 U3.5(OSC_OUT) Y2.3
LINK_LED: J11#1.6 U3.43(LINKLED)
RXI_N: J11#1.1 U3.56(RXIN)
RXI_P: J11#1.3 U3.55(RXIP)
SPEED_LED: J11#1.8 U3.42(SPDLED)
TXO_N: J11#1.5 U3.53(TXON)
TXO_P: J11#1.7 U3.52(TXOP)
USB_COMM_N: C39.2 R27.2 U3.27(PA11/USB_DM)
USB_COMM_P: C40.2 R26.2 U3.28(PA12/USB_DP)
USB_EXT_N: J1.2(D-) R27.1
USB_EXT_P: J1.3(D+) R26.1
NetC4_2: C4.2 R25.2 Y1.3
NetC5_2: C5.2 R21.1 U3.39(W_XI) Y1.1
NetC43_2: C43.2 C44.2 U3.50(XTALVDD)
NetJ12_2: J12.2 R43.1
NetR21_2: R21.2 R25.1 U3.40(W_XO)
NetR22_2: U3.36(PB6) ; port ~{RESET}
NetR24_1: R24.1 U3.15(PB2/BOOT1)
NetR29_1: R29.1 U3.44(MDC)
NetR30_1: R30.1 U3.58(ANE)
NetR32_1: R32.1 U3.51(W_RESET)
NetR33_1: R33.1 U3.54(W_PWDN)
NetR39_1: R39.1 U3.48(W_BIAS)
NetR40_2: R40.2 U3.41(FDXLED)
NetR41_2: R41.2 U3.60(SPD)
NetR42_2: R42.2 U3.59(DUP)

Not connected (* = marked no-connect by the designer): J1 4(ID)*; J14 7*; S3 1(A)*; U3 2(PC14/OSC32_IN)* 3(PC15/OSC32_OUT)* 9(PA0/WKUP)* 10(PA1)* 11(PA2)* 12(PA3)* 13(PB0) 16(PB10)* 17(PB11)* 20(PB12/SPI2_NSS)* 21(PB13/SPI2_SCK)* 22(PB14/SPI2_MISO)* 23(PB15/SPI2_MOSI)* 24(PA8)* 37(PB7) 45(MDIO)*

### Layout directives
differential pair: RXI_N, RXI_P, TXO_N, TXO_P, USB_COMM_N, USB_COMM_P, USB_EXT_N, USB_EXT_P

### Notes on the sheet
- This processor will be configured as a slave SPI device, confirm the correct connection in order to allow the main processor to interface with this device
  SLAVE MODE!
  MISO: OUTPUT
  MOSI: INPUT
- (near C4) 0 Ohm Resistor may not be needed in production but should be used within the prototype to determine if the inverter output current needs to be limited
- BOOT Modes
  B0	B1
  0	X	Flash Memory
  1	0	System Memory
  1	1	Embedded SRAM
- (near U3) What is the function of
  MDIO: For MII interface
  MDC: For MII interface
  ANE:
  SPD: 100 ??
  DUP: Duplex??
- RESET and BOOT0 may not be selectable in the production version but will allow for debugging during prototype phase
- Confirm that this jack will work.
  It conforms to the symmetric jack described in the datasheet
- 4.7uF must be across VDD_3V3

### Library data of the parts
C4 C5 C60 C61 = C_0402_18PF_50V: as C62 on sheet MAPLE_II_PROCESSOR
C39 C40 = C_0402_47p_50V: CAP CER 47PF 50V 5% C0G 0402; Manufacturer: Murata Electronics North America; Manufacturer Part Number: GRM1555C1H470JZ01D
C42 C44-C46 C59 = C_0402_0.1UF_16V: as C41 on sheet MAPLE_II_PROCESSOR
C43 = C_0805_10UF_6.3V: CAP CER 10UF 6.3V X7R 10% 0805; Manufacturer: AVX Corporation; Manufacturer Part Number: 08056C106KAT2A
C47 C48 C50 C53 C55 C57 = C_0201_0.1UF: as C16 on sheet MAPLE_II_PROCESSOR
C49 C51 C54 C56 C58 = C_0201_0.01UF: CAP CER 10000PF 6.3V X5R 0201; Manufacturer: TDK Corporation; Manufacturer Part Number: C0603X5R0J103M; Tolerance: ±20%
C52 = C_0402_4.7UF: as C19 on sheet MAPLE_II_PROCESSOR
FB1 FB2 = FB_0603_120_100MHZ: FERRITE CHIP 120 OHM 2000MA 0603; Manufacturer: Murata Electronics North America; Manufacturer Part Number: BLM18PG121SN1D; DC Resistance (DCR): 50 mOhm Max; Filter Type: Differential Mode - Single; Number of Lines: 1
J1 = J_A31727TR-ND: CONN MINI USB RCPT RA TYPE B SMD; Number of Contacts: 5; Specifications: USB 2.0
J11#1 = J_HDR2X4_0.05_RCP_SMD: CONN RECEPT 8POS DUAL SMD; Manufacturer: FCI; Manufacturer Part Number: 20021321-00008C4LF; Connector Type: Receptacle; Number of Positions Loaded: All
J11#2 = J_ETH_J0011D01B: CONN PULSEJACK 1PORT 10/100B-TX; Number of Ports: 1; LED Color: Green - Yellow; Number of Cores per Jack: 4; Shielding: Unshielded; Tab Direction: Down
J12 = J_HDR1X3_JUMPER_SELECT: CONN HEADER .100" 12POS TIN PCB; Manufacturer: Samtec Inc; Manufacturer Part Number: TS-112-T-A; Connector Type: Unshrouded; Number of Positions: 12; Number of Positions Loaded: All
J14 = J_HDR2X5_0.05_SMD: as J9 on sheet MAPLE_II_PROCESSOR
R21 = R_1206_1.0M: RES 1.00M OHM 1/4W 1% 1206 SMD; Manufacturer: Panasonic - ECG; Manufacturer Part Number: ERJ-8GEYJ105V; Description: RES 1.0M OHM 1/4W 5% 1206 SMD; Temperature Coefficient: ±200ppm/°C; Tolerance: ±5%
R24 R29 R30 R32 R33 R40-R43 = R_0402_10.0K: as R15 on sheet MAPLE_II_PROCESSOR
R25 = R_0402_0.00: as R17 on sheet MAPLE_II_PROCESSOR
R26 R27 = R_0402_22.0: RES 22.0 OHM 1/16W 1% 0402 SMD; Manufacturer: Yageo; Manufacturer Part Number: RC0402FR-0722RL; Temperature Coefficient: ±100ppm/°C
R31#2 R38 = R_0402_200.0: RES 200 OHM 1/10W 1% 0402 SMD; Manufacturer: Panasonic - ECG; Manufacturer Part Number: ERJ-2RKF2000X; Temperature Coefficient: ±100ppm/°C
R34#2 R35#2 R36 R37 = R_0402_49.9: as R16 on sheet MAPLE_II_PROCESSOR
R39 = R_0402_28.7K: RES 28.7K OHM 1/16W 1% 0402 SMD; Manufacturer: Vishay/Dale; Manufacturer Part Number: CRCW040228K7FKED; Temperature Coefficient: ±100ppm/°C
S3 = S_TACTILE_5X5: as S2 on sheet MAPLE_II_PROCESSOR
U3 = U_W7200: WIZNET 7200 MCU INT TCP/IP STACK
Y1 = Y_SMD_25.00MHZ_18PF: CRYSTAL 25.000000 MHZ 8PF SMD; Manufacturer: CTS-Frequency Controls; Manufacturer Part Number: 405C35D25M00000; Description: CRYSTAL 25.0 MHZ 18 PF SMD; Frequency Stability: ±50ppm; Frequency Tolerance: ±30ppm; Load Capacitance: 18pF; Operating Mode: Fundamental
Y2 = Y_SMD_8.00MHZ_10PF: as Y3 on sheet MAPLE_II_PROCESSOR

## Sheet MAPLE_II_POWER.SchDoc: Power
size B; CompanyName: LeafLabs; DrawnBy: David McCoy; Engineer: David McCoy; Organization: LeafLabs; DocumentNumber: 5; Revision: A; SheetNumber: 5; SheetTotal: 6; ProjectPrettyName: Maple II
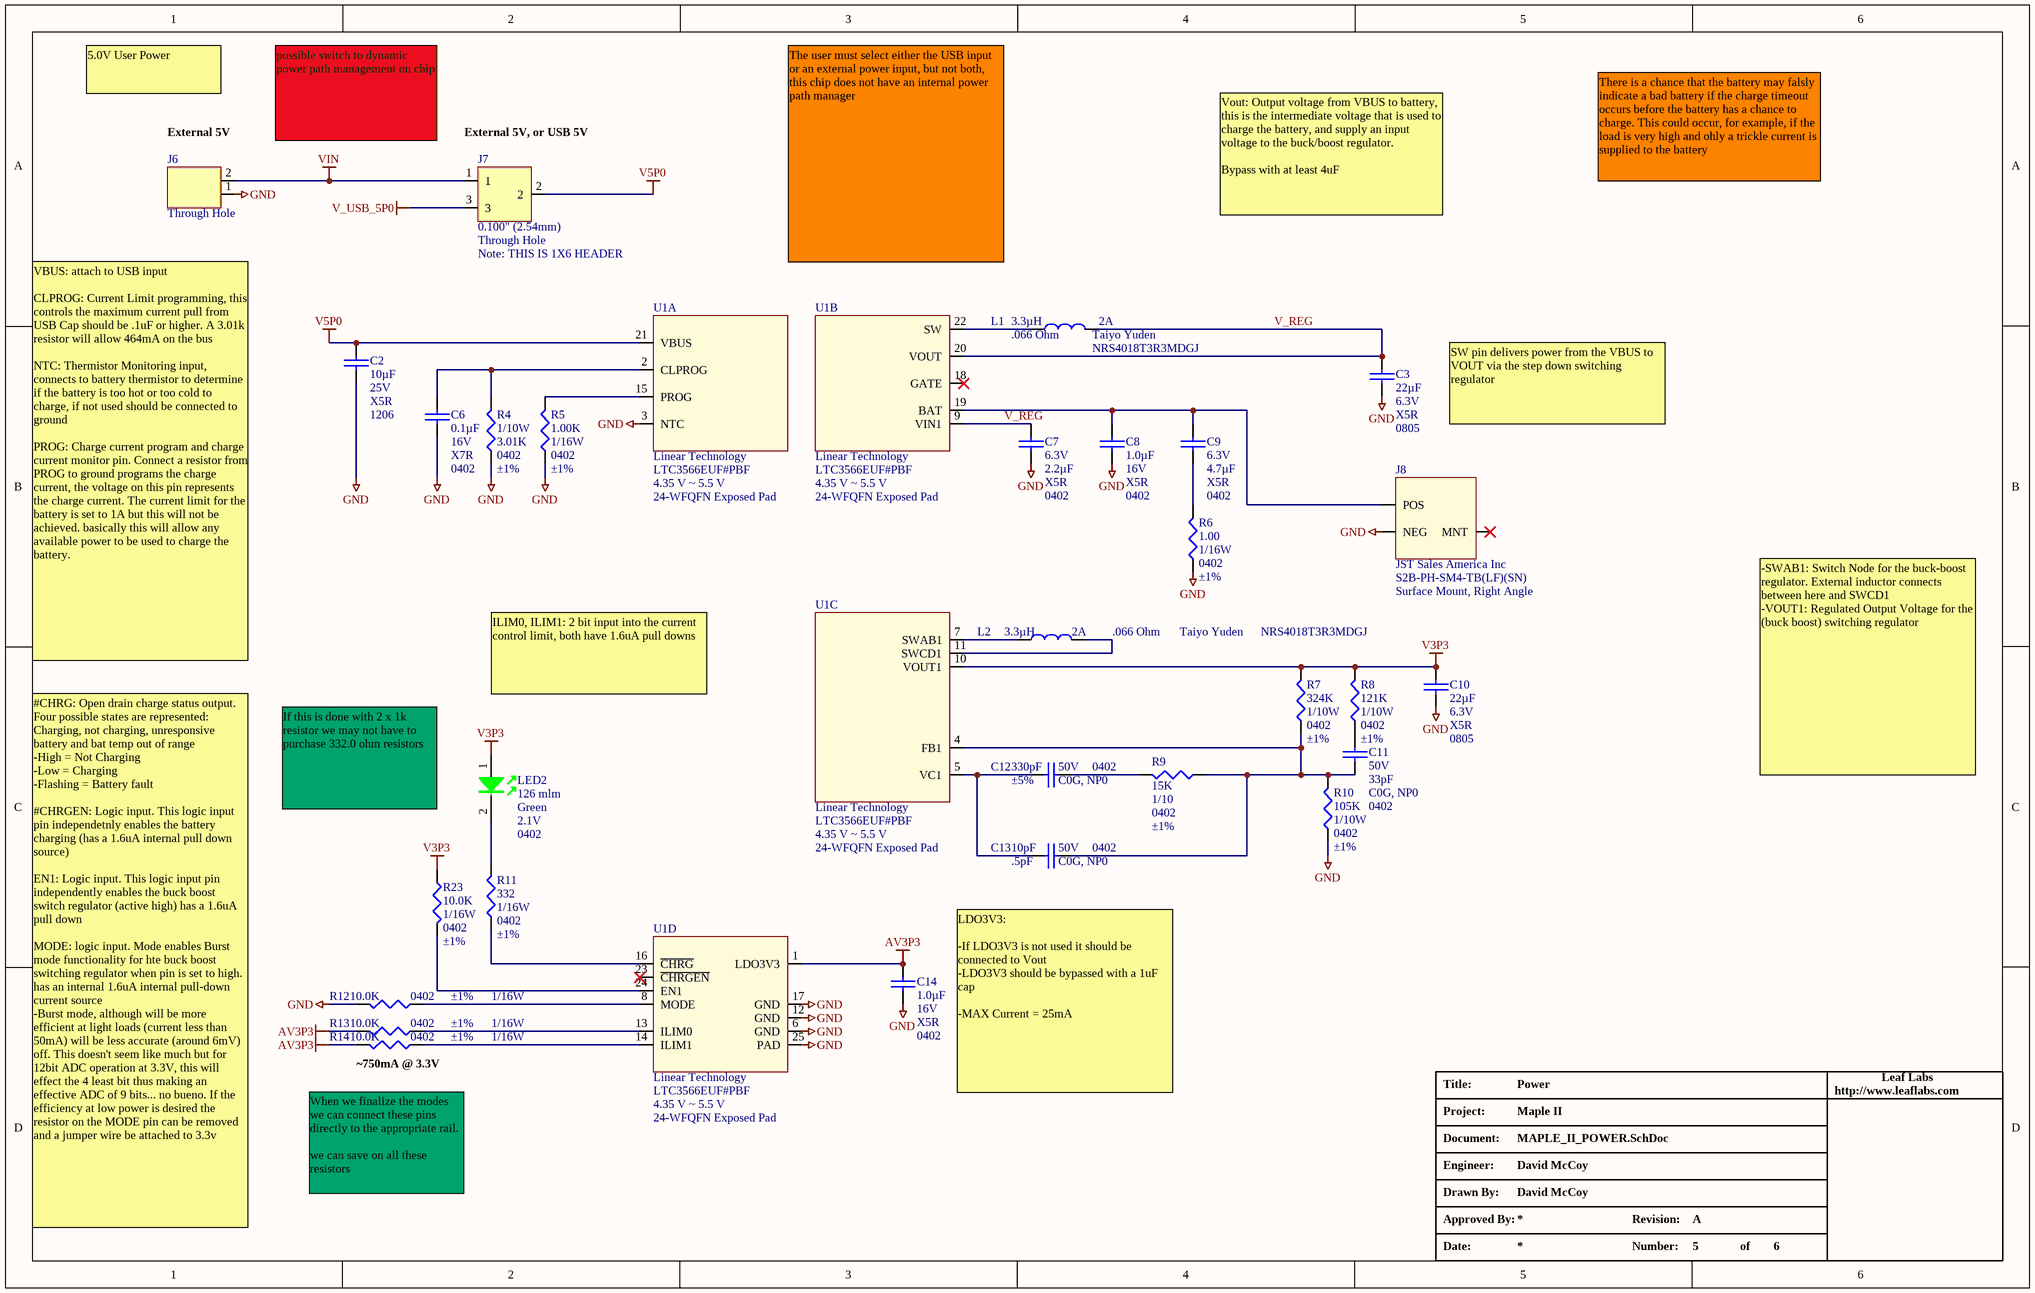
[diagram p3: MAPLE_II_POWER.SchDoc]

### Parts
C2  Voltage - Rated: 25V  Temperature Coefficient: X5R  Package / Case: 1206  [CAP-1206]  (hidden comment: 10µF)
C3  Capacitance: 22µF  Voltage - Rated: 6.3V  Temperature Coefficient: X5R  Package / Case: 0805  [C_ERA-0805]  (hidden comment: C_0805_22uF_25V)
C6  Capacitance: 0.1µF  Voltage - Rated: 16V  Temperature Coefficient: X7R  Package / Case: 0402  [C_ERA-0402]  (hidden comment: Capacitor 0.1uF 0402 16V)
C7  Voltage - Rated: 6.3V  Capacitance: 2.2µF  Temperature Coefficient: X5R  Package / Case: 0402  [C_ERA-0402]  (hidden comment: Capacitor 2.2uF 0402)
C8  Capacitance: 1.0µF  Voltage - Rated: 16V  Temperature Coefficient: X5R  Package / Case: 0402  [C_ERA-0402]  (hidden comment: Capacitor 1.0uF 0402 16V)
C9  Voltage - Rated: 6.3V  Capacitance: 4.7µF  Temperature Coefficient: X5R  Package / Case: 0402  [C_ERA-0402]  (hidden comment: Capacitor  4.7uF 0402)
C10  Capacitance: 22µF  Voltage - Rated: 6.3V  Temperature Coefficient: X5R  Package / Case: 0805  [C_ERA-0805]  (hidden comment: C_0805_22uF_25V)
C11  Voltage - Rated: 50V  Capacitance: 33pF  Temperature Coefficient: C0G, NP0  Package / Case: 0402  [C_ERA-0402]  (hidden comment: Capacitor 33pF 0402)
C12  Capacitance: 330pF  Voltage - Rated: 50V  Tolerance: ±5%  Temperature Coefficient: C0G, NP0  Package / Case: 0402  [C_ERA-0402]  (hidden comment: Capacitor 330pF 0402)
C13  Capacitance: 10pF  Voltage - Rated: 50V  Tolerance: .5pF  Temperature Coefficient: C0G, NP0  Package / Case: 0402  [C_ERA-0402]  (hidden comment: Capacitor 10pF 0402)
C14  Capacitance: 1.0µF  Voltage - Rated: 16V  Temperature Coefficient: X5R  Package / Case: 0402  [C_ERA-0402]  (hidden comment: Capacitor 1.0uF 0402 16V)
J6  Mounting Type: Through Hole  [HDR_1X2]  (hidden comment: J_HDR1X2_JUMPER)
J7  Pitch: 0.100" (2.54mm)  Mounting Type: Through Hole  Note: THIS IS 1X6 HEADER  [HDR_1X3]  (hidden comment: J_HDR1X3_JUMPER_SELECT)
J8  Manufacturer: JST Sales America Inc  Manufacturer Part Number: S2B-PH-SM4-TB(LF)(SN)  Mounting Type: Surface Mount, Right Angle  [HDR_1X2_LIPO_BATTERY]  (hidden comment: J_LIPO_BAT_CONNECTOR)
L1  Manufacturer: Taiyo Yuden  Manufacturer Part Number: NRS4018T3R3MDGJ  Inductance: 3.3µH  Current: 2A  DC Resistance (DCR): .066 Ohm  [INDP4040X120L]  (hidden comment: 3.3UH 66 mOhm)
L2  Manufacturer: Taiyo Yuden  Manufacturer Part Number: NRS4018T3R3MDGJ  Inductance: 3.3µH  Current: 2A  DC Resistance (DCR): .066 Ohm  [INDP4040X120L]  (hidden comment: 3.3UH 66 mOhm)
LED2  Luminous Flux @ Current - Test: 126 mlm  Color: Green  Voltage - Forward (Vf) Typ: 2.1V  Package / Case: 0402  [DIOM1005X07L_GREEN]  (hidden comment: LED_GRN_0402)
R4  Power (Watts): 1/10W  Resistance In Ohms: 3.01K  Case: 0402  Tolerance: ±1%  [ERA-0402]  (hidden comment: R_0402_3.01K)
R5  Resistance In Ohms: 1.00K  Power (Watts): 1/16W  Case: 0402  Tolerance: ±1%  [ERA-0402]  (hidden comment: R_0402_1.0K)
R6  Resistance In Ohms: 1.00  Power (Watts): 1/16W  Case: 0402  Tolerance: ±1%  [ERA-0402]  (hidden comment: R_0402_1.00)
R7  Resistance In Ohms: 324K  Power (Watts): 1/10W  Case: 0402  Tolerance: ±1%  [ERA-0402]  (hidden comment: R_0402_324.0K)
R8  Resistance In Ohms: 121K  Power (Watts): 1/10W  Case: 0402  Tolerance: ±1%  [ERA-0402]  (hidden comment: R_0402_121.0K)
R9  Resistance In Ohms: 15K  Power (Watts): 1/10  Case: 0402  Tolerance: ±1%  [ERA-0402]  (hidden comment: R_0402_15.0K)
R10  Resistance In Ohms: 105K  Power (Watts): 1/10W  Case: 0402  Tolerance: ±1%  [ERA-0402]  (hidden comment: R_0402_105.0K)
R11  Resistance In Ohms: 332  Power (Watts): 1/16W  Case: 0402  Tolerance: ±1%  [ERA-0402]  (hidden comment: R_0402_332.0)
R12  Resistance In Ohms: 10.0K  Power (Watts): 1/16W  Case: 0402  Tolerance: ±1%  [ERA-0402]  (hidden comment: R_0402_10.0K)
R13  Resistance In Ohms: 10.0K  Power (Watts): 1/16W  Case: 0402  Tolerance: ±1%  [ERA-0402]  (hidden comment: R_0402_10.0K)
R14  Resistance In Ohms: 10.0K  Power (Watts): 1/16W  Case: 0402  Tolerance: ±1%  [ERA-0402]  (hidden comment: R_0402_10.0K)
R23  Resistance In Ohms: 10.0K  Power (Watts): 1/16W  Case: 0402  Tolerance: ±1%  [ERA-0402]  (hidden comment: R_0402_10.0K)
U1  Manufacturer: Linear Technology  Manufacturer Part Number: LTC3566EUF#PBF  Voltage - Supply: 4.35 V ~ 5.5 V  Package / Case: 24-WFQFN Exposed Pad  [QFN50P400X400X100-24L]  (hidden comment: 5V USB/DC Bat Charger PMIC)  (parts A,B,C,D of 4)

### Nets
AV3P3: C14.2 R13.1 R14.1 U1.1(LDO3V3)
GND: C2.1 C3.1 C6.1 C7.1 C8.1 C10.1 C14.1 J6.1 J8.2(NEG) R4.2 R5.2 R6.2 R10.2 R12.1 U1.3(NTC) U1.6(GND) U1.12(GND) U1.17(GND) U1.25(PAD)
V3P3: C10.2 LED2.1 R7.1 R8.1 R23.2 U1.10(VOUT1)
V5P0: C2.2 J7.2 U1.21(VBUS)
V_USB_5P0: J7.3
VIN: J6.2 J7.1
V_REG: C3.2 C7.2 L1.2 U1.9(VIN1) U1.20(VOUT)
NetC6_2: C6.2 R4.1 U1.2(CLPROG)
NetC8_2: C8.2 C9.2 J8.1(POS) U1.19(BAT)
NetC9_1: C9.1 R6.1
NetC11_1: C11.1 C13.1 R7.2 R9.2 R10.1 U1.4(FB1)
NetC11_2: C11.2 R8.2
NetC12_1: C12.1 R9.1
NetC12_2: C12.2 C13.2 U1.5(VC1)
NetL1_1: L1.1 U1.22(SW)
NetL2_1: L2.1 U1.7(SWAB1)
NetL2_2: L2.2 U1.11(SWCD1)
NetLED2_2: LED2.2 R11.1
NetR5_1: R5.1 U1.15(PROG)
NetR11_2: R11.2 U1.16(~{CHRG})
NetR12_2: R12.2 U1.8(MODE)
NetR13_2: R13.2 U1.13(ILIM0)
NetR14_2: R14.2 U1.14(ILIM1)
NetR23_1: R23.1 U1.24(EN1)

Not connected (* = marked no-connect by the designer): J8 MNT*; U1 18(GATE)* 23(~{CHRGEN})*

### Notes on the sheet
- 5.0V User Power
- (near J6) External 5V
- possible switch to dynamic power path management on chip
- (near J7) External 5V, or USB 5V
- Vout: Output voltage from VBUS to battery, this is the intermediate voltage that is used to charge the battery, and supply an input voltage to the buck/boost regulator.
  Bypass with at least 4uF
- There is a chance that the battery may falsly indicate a bad battery if the charge timeout occurs before the battery has a chance to charge. This could occur, for example, if the load is very high and ohly a trickle current is supplied to the battery
- The user must select either the USB input or an external power input, but not both, this chip does not have an internal power path manager
- SW pin delivers power from the VBUS to  VOUT via the step down switching regulator
- VBUS: attach to USB input
  CLPROG: Current Limit programming, this controls the maximum current pull from USB Cap should be .1uF or higher. A 3.01k resistor will allow 464mA on the bus
  NTC: Thermistor Monitoring input, connects to battery thermistor to determine if the battery is too hot or too cold to charge, if not used should be connected to ground
  PROG: Charge current program and charge current monitor pin. Connect a resistor from PROG to ground programs the charge current, the voltage on this pin represents the charge current. The current limit for the battery is set to 1A but this will not be achieved. basically this will allow any available power to be used to charge the battery.
- ILIM0, ILIM1: 2 bit input into the current control limit, both have 1.6uA pull downs
- -SWAB1: Switch Node for the buck-boost regulator. External inductor connects between here and SWCD1
  -VOUT1: Regulated Output Voltage for the (buck boost) switching regulator
- If this is done with 2 x 1k resistor we may not have to purchase 332.0 ohm resistors
- (near R14) ~750mA @ 3.3V
- LDO3V3:
  -If LDO3V3 is not used it should be connected to Vout
  -LDO3V3 should be bypassed with a 1uF cap
  -MAX Current = 25mA
- #CHRG: Open drain charge status output. Four possible states are represented: Charging, not charging, unresponsive battery and bat temp out of range
  -High = Not Charging
  -Low = Charging
  -Flashing = Battery fault
  #CHRGEN: Logic input. This logic input pin independetnly enables the battery charging (has a 1.6uA internal pull down source)
  EN1: Logic input. This logic input pin independently enables the buck boost switch regulator (active high) has a 1.6uA pull down
  MODE: logic input. Mode enables Burst mode functionality for hte buck boost switching regulator when pin is set to high. has an internal 1.6uA internal pull-down current source
  -Burst mode, although will be more efficient at light loads (current less than 50mA) will be less accurate (around 6mV) off. This doesn't seem like much but for 12bit ADC operation at 3.3V, this will effect the 4 least bit thus making an effective ADC of 9 bits... no bueno. If the efficiency at low power is desired the resistor on the MODE pin can be removed and a jumper wire be attached to 3.3v
- When we finalize the modes we can connect these pins directly to the appropriate rail.
  we can save on all these resistors

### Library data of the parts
C2 = C_1206_10UF_25V: CAP CER 10UF 25V X5R 1206; Manufacturer: Murata Electronics North America; Manufacturer Part Number: GRM31CR61E106MA12L; Tolerance: ±20%
C3 C10 = C_0805_22UF_6.3V: CAP CER 22UF 6.3V X7R 10% 0805; Manufacturer: AVX Corporation; Manufacturer Part Number: 08056D226MAT2A; Description: CAP CERM 22UF 20% 6.3V X5R 0805; Tolerance: ±20%
C6 = C_0402_0.1UF_16V: as C41 on sheet MAPLE_II_PROCESSOR
C7 = C_0402_2.2UF: as C17 on sheet MAPLE_II_PROCESSOR
C8 C14 = C_0402_1.0UF_16V: CAP CER 1.0UF 16V X5R 0402; Manufacturer: TDK Corporation; Manufacturer Part Number: C1005X5R1C105K; Tolerance: ±10%
C9 = C_0402_4.7UF: as C19 on sheet MAPLE_II_PROCESSOR
C11 = C_0402_33PF: CAP CER 33PF 50V C0G 5% 0402; Manufacturer: TDK Corporation; Manufacturer Part Number: C1005C0G1H330J
C12 = C_0402_330PF_50V: CAP CER 330PF 50V 5% NP0 0402; Manufacturer: Taiyo Yuden; Manufacturer Part Number: UMK105CG331JV-F
C13 = C_0402_10PF_50V: CAP CER 10PF 50V NP0 0402; Manufacturer: Taiyo Yuden; Manufacturer Part Number: UMK105CG100DV-F
J6 = J_HDR1X2_JUMPER: as J10 on sheet MAPLE_II_PROCESSOR
J7 = J_HDR1X3_JUMPER_SELECT: CONN HEADER .100" 12POS TIN PCB; Manufacturer: Samtec Inc; Manufacturer Part Number: TS-112-T-A; Connector Type: Unshrouded; Number of Positions: 12; Number of Positions Loaded: All; NOTE: This is a 1x12 header
J8 = J_LIPO_BAT_CONNECTOR: CONN HEADER PH SIDE 2POS 2MM SMD; Connector Type: Header, Shrouded; Number of Positions: 2; Number of Positions Loaded: All; Pitch: 0.079" (2.00mm)
L1 L2 = L_3.30UH_2A: INDUCTOR POWER 3.3UH 2.0A SMD; Current - Saturation: 2.3A; Tolerance: ±20%; Shielding: Shielded; Frequency - Self Resonant: 45MHz; Frequency - Test: 100kHz
LED2 = LED_GRN_0402: LED 1X0.5MM 570NM GN WTR CLR SMD; Manufacturer: Kingbright Corp; Manufacturer Part Number: APHHS1005CGCK; Current - Test: 20mA; Wavelength - Peak: 574nm; Millicandela Rating: 40mcd; Lens Type: Clear; Lens Style/Size: Rectangle, 0.8mm x 0.5mm; Viewing Angle: 120°
R4 = R_0402_3.01K: RES 3.01K OHM 1/16W 1% 0402 SMD; Manufacturer: Stackpole Electronics Inc; Manufacturer Part Number: RMCF0402FT3K01; Description: RES TF 3.01K OHM 1% 1/16W 0402; Temperature Coefficient: ±100ppm/°C
R5 = R_0402_1.0K: as R20 on sheet MAPLE_II_PROCESSOR
R6 = R_0402_1.00: RES 1.00 OHM 1/16W 1% 0402 SMD; Manufacturer: Yageo; Manufacturer Part Number: RC0402FR-071RL; Temperature Coefficient: ±200ppm/°C
R7 = R_0402_324.0K: RES 324K OHM 1/10W 1% 0402 SMD; Manufacturer: Panasonic - ECG; Manufacturer Part Number: ERJ-2RKF3243X; Temperature Coefficient: ±100ppm/°C
R8 = R_0402_121.0K: RES 121K OHM 1/10W 1% 0402 SMD; Manufacturer: Panasonic - ECG; Manufacturer Part Number: ERJ-2RKF1213X; Temperature Coefficient: ±100ppm/°C
R9 = R_0402_15.0K: RES 15.0K OHM 1/10W 1% 0402 SMD; Manufacturer: Panasonic - ECG; Manufacturer Part Number: ERJ-2RKF1502X; Temperature Coefficient: ±100ppm/°C
R10 = R_0402_105.0K: RES 105K OHM 1/10W 1% 0402 SMD; Manufacturer: Panasonic - ECG; Manufacturer Part Number: ERJ-2RKF1053X; Temperature Coefficient: ±100ppm/°C
R11 = R_0402_332.0: RES 332 OHM 1/16W 1% 0402 SMD; Manufacturer: Vishay/Dale; Manufacturer Part Number: CRCW0402332RFKED; Temperature Coefficient: ±100ppm/°C
R12-R14 R23 = R_0402_10.0K: as R15 on sheet MAPLE_II_PROCESSOR
U1 = U_LTC3566: IC USB POWER MANAGER 24-QFN

## Sheet MAPLE_II_EXPANSION.SchDoc: Expansion
size B; CompanyName: LeafLabs; DrawnBy: David McCoy; Engineer: David McCoy; Organization: LeafLabs; DocumentNumber: 4; Revision: A; SheetNumber: 4; SheetTotal: 6; ProjectPrettyName: Maple II
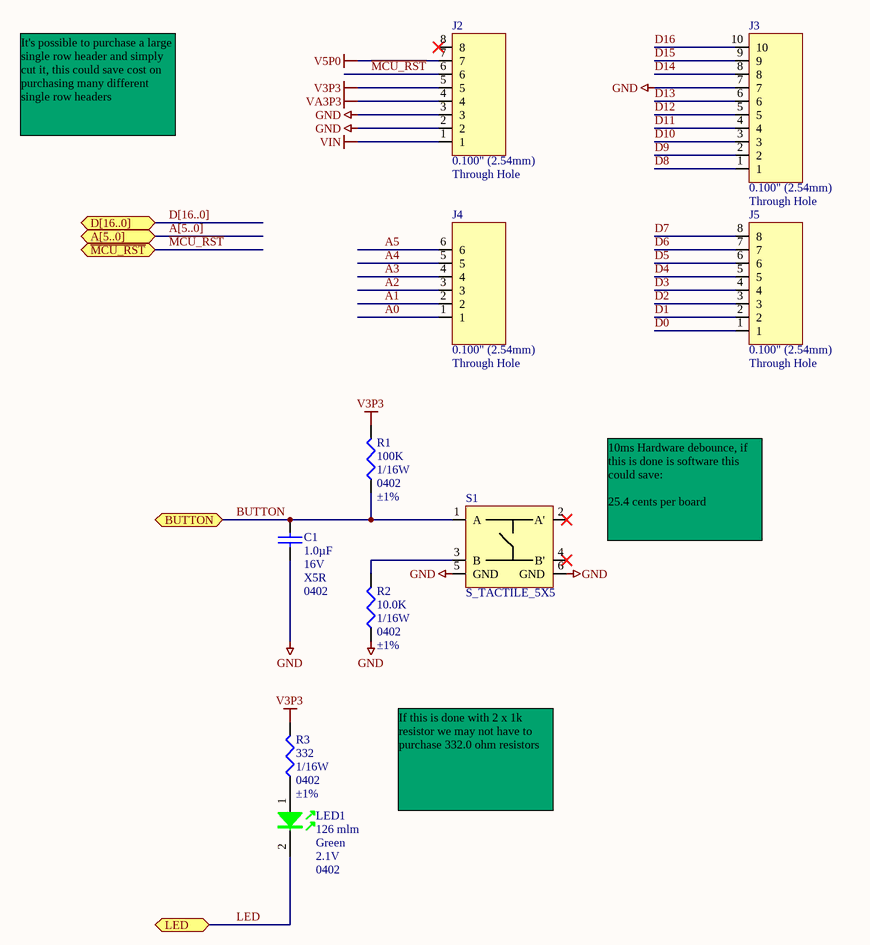
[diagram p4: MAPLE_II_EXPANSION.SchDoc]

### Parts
C1  Capacitance: 1.0µF  Voltage - Rated: 16V  Temperature Coefficient: X5R  Package / Case: 0402  [C_ERA-0402]  (hidden comment: Capacitor 1.0uF 0402 16V)
J2  Pitch: 0.100" (2.54mm)  Mounting Type: Through Hole  [HDR_1X8 - FEMALE]  (hidden comment: J_HDR1X8_THRHOLE_VERT_RECPT)
J3  Pitch: 0.100" (2.54mm)  Mounting Type: Through Hole  [HDR_1X10 - FEMALE]  (hidden comment: J_HDR1X8_THRHOLE_VERT_RECPT)
J4  Pitch: 0.100" (2.54mm)  Mounting Type: Through Hole  [HDR_1X6 - FEMALE]  (hidden comment: J_HDR1X6_THRHOLE_VERT_FEMALE)
J5  Pitch: 0.100" (2.54mm)  Mounting Type: Through Hole  [HDR_1X8 - FEMALE]  (hidden comment: J_HDR1X8_THRHOLE_VERT_RECPT)
LED1  Luminous Flux @ Current - Test: 126 mlm  Color: Green  Voltage - Forward (Vf) Typ: 2.1V  Package / Case: 0402  [DIOM1005X07L_GREEN]  (hidden comment: LED_GRN_0402)
R1  Resistance In Ohms: 100K  Power (Watts): 1/16W  Case: 0402  Tolerance: ±1%  [ERA-0402]  (hidden comment: R_0402_100.0K)
R2  Resistance In Ohms: 10.0K  Power (Watts): 1/16W  Case: 0402  Tolerance: ±1%  [ERA-0402]  (hidden comment: R_0402_10.0K)
R3  Resistance In Ohms: 332  Power (Watts): 1/16W  Case: 0402  Tolerance: ±1%  [ERA-0402]  (hidden comment: R_0402_332.0)
S1  S_TACTILE_5X5  [TACTILE_BUTTON_5X5]

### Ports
A[5..0], BUTTON, D[16..0], LED, ~{MCU_RST}

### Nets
GND: C1.1 J2.2 J2.3 J3.7 R2.2 S1.5(GND) S1.6(GND)
V3P3: J2.5 R1.1 R3.1
V5P0: J2.7
VA3P3: J2.4
VIN: J2.1
A0: J4.1
A1: J4.2
A2: J4.3
A3: J4.4
A4: J4.5
A5: J4.6
BUTTON: C1.2 R1.2 S1.1(A) ; port BUTTON  [project net BOOT0]
D0: J5.1
D1: J5.2
D2: J5.3
D3: J5.4
D4: J5.5
D5: J5.6
D6: J5.7
D7: J5.8
D8: J3.1
D9: J3.2
D10: J3.3
D11: J3.4
D12: J3.5
D13: J3.6 LED1.2 ; port LED  [also labelled LED]
D14: J3.8
D15: J3.9
D16: J3.10
~{MCU_RST}: J2.6 ; port ~{MCU_RST}
NetLED1_1: LED1.1 R3.2
NetR2_1: R2.1 S1.3(B)

Not connected (* = marked no-connect by the designer): J2 8*; S1 2(A')* 4(B')*

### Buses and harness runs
bus A[5..0] = port A[5..0]
bus D[16..0] = port D[16..0]

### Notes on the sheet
- It's possible to purchase a large single row header and simply cut it, this could save cost on purchasing many different single row headers
- 10ms Hardware debounce, if this is done is software this could save:
  25.4 cents per board
- If this is done with 2 x 1k resistor we may not have to purchase 332.0 ohm resistors

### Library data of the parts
C1 = C_0402_1.0UF_16V: as C8 on sheet MAPLE_II_POWER
J2 J5 = J_HDR1X8_THRHOLE_VERT_FEMALE: CONN HEADER FEMALE 8POS .1" TIN; Manufacturer: Sullins Connector Solutions; Manufacturer Part Number: PPTC081LFBN-RC; Number of Positions: 8; Number of Positions Loaded: All
J3 = J_HDR1X10_THRHOLE_VERT_FEMALE: CONN HEADER FEMALE 10POS.1" TIN
J4 = J_HDR1X6_THRHOLE_VERT_FEMALE: CONN HEADER FEMALE 6POS .1" TIN; Manufacturer: Sullins Connector Solutions; Manufacturer Part Number: PPTC061LFBN-RC; Number of Positions: 6; Number of Positions Loaded: All
LED1 = LED_GRN_0402: as LED2 on sheet MAPLE_II_POWER
R1 = R_0402_100.0K: RES 100K OHM 1/16W 1% 0402 SMD; Manufacturer: Vishay/Dale; Manufacturer Part Number: CRCW0402100KFKED; Temperature Coefficient: ±100ppm/°C
R2 = R_0402_10.0K: as R15 on sheet MAPLE_II_PROCESSOR
R3 = R_0402_332.0: as R11 on sheet MAPLE_II_POWER
S1 = S_TACTILE_5X5: as S2 on sheet MAPLE_II_PROCESSOR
